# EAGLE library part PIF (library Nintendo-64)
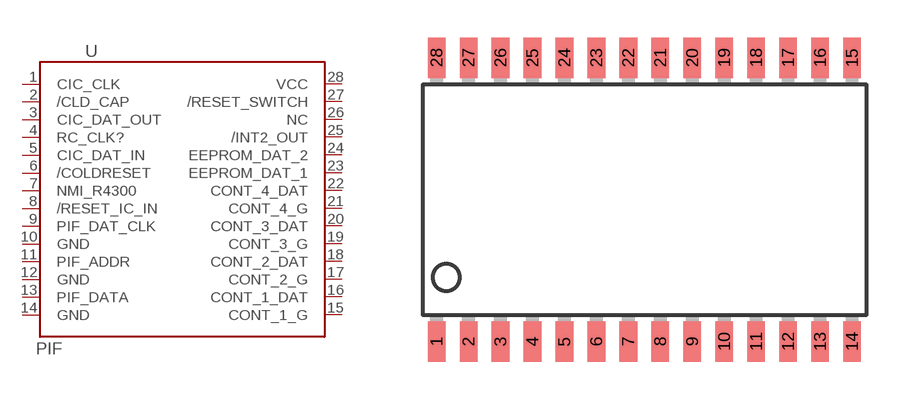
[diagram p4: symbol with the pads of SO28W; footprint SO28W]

Designator prefix -

## PIF  [SO28W]
1  CIC_CLK  out
2  /CLD_CAP  in
3  CIC_DAT_OUT  out
4  RC_CLK?  out
5  CIC_DAT_IN  in
6  /COLDRESET  out
7  NMI_R4300  out
8  /RESET_IC_IN  in
9  PIF_DAT_CLK  in
10  GND  pwr
11  PIF_ADDR  in
12  GND  pwr
13  PIF_DATA  out
14  GND  pwr
15  CONT_1_G  out
16  CONT_1_DAT  in
17  CONT_2_G  out
18  CONT_2_DAT  in
19  CONT_3_G  out
20  CONT_3_DAT  in
21  CONT_4_G  out
22  CONT_4_DAT  in
23  EEPROM_DAT_1
24  EEPROM_DAT_2
25  /INT2_OUT  out
26  NC  nc
27  /RESET_SWITCH  in
28  VCC  pwr

## Footprint SO28W (pad centres in mm)
smd 0.7 x 1.6: 1 -8.89,-5.707; 2 -7.62,-5.707; 3 -6.35,-5.707; 4 -5.08,-5.707; 5 -3.81,-5.707; 6 -2.54,-5.707; 7 -1.27,-5.707; 8 0,-5.707; 9 1.27,-5.707; 10 2.54,-5.707; 11 3.81,-5.707; 12 5.08,-5.707; 13 6.35,-5.707; 14 7.62,-5.707; 15 7.62,5.58; 16 6.35,5.58; 17 5.08,5.58; 18 3.81,5.58; 19 2.54,5.58; 20 1.27,5.58; 21 0,5.58; 22 -1.27,5.58; 23 -2.54,5.58; 24 -3.81,5.58; 25 -5.08,5.58; 26 -6.35,5.58; 27 -7.62,5.58; 28 -8.89,5.58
